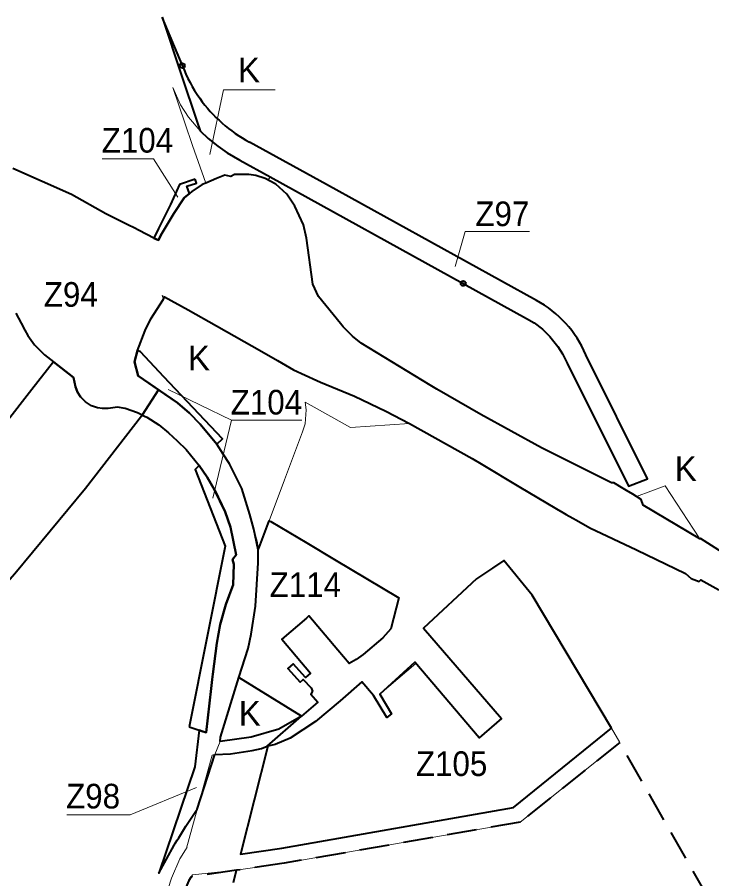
# Model space of a CAD drawing. Extents: x -650276 to -642489, y -1074311 to -1066658.
# Drawn here: x -646740 to -646064, y -1069193 to -1068354 of the extents above; entities that cross this region are included whole.
import ezdxf

# ---------------------------------------------------------------- set-up
doc = ezdxf.new("R2010")
doc.units = 0
doc.header["$LTSCALE"] = 9.6
doc.header["$PDMODE"] = 32
doc.header["$PDSIZE"] = 4.8
doc.linetypes.add('MEDIUM_DASHED', pattern=[4.5, 3, -1.5])
for name, color, linetype, lineweight in [('44', 7, 'Continuous', 40), ('45', 7, 'Continuous', 40), ('46', 7, 'Continuous', 13), ('47', 7, 'Continuous', 13), ('48', 7, 'Continuous', 13), ('61', 7, 'MEDIUM_DASHED', 40), ('63', 7, 'Continuous', 13)]:
    doc.layers.add(name, color=color, linetype=linetype, lineweight=lineweight)

msp = doc.modelspace()

# ---------------------------------------------------------------- linework, layer by layer
at = {"layer": '44'}
msp.add_line((-646578.881, -1068401.54), (-646598.635, -1068354.436), dxfattribs=at)
for points in [[(-646598.635, -1068354.436), (-646579.62, -1068411.29), (-646564.78, -1068455.41), (-646561.544, -1068464.842)], [(-646561.544, -1068464.842), (-646553.677, -1068472.283), (-646544.525, -1068479.79), (-646535.245, -1068486.342), (-646523.105, -1068493.54), (-646493.511, -1068509.855), (-646305.678, -1068613.404)], [(-646234.342, -1068629.893), (-646234.342, -1068629.892), (-646438.626, -1068517.274), (-646513.45, -1068476.025), (-646513.567, -1068475.963)], [(-646545.57, -1068511.42), (-646556.22, -1068515.84), (-646559.72, -1068517.29), (-646569.61, -1068524.1), (-646572.02, -1068526.07), (-646577.07, -1068530.2), (-646587.28, -1068545.28), (-646599.75, -1068566.49), (-646602.21, -1068571.5), (-646606.59, -1068569.33), (-646620.94, -1068561.96), (-646625.86, -1068559.47), (-646631.18, -1068556.77), (-646653.21, -1068545.58), (-646686.84, -1068526.89), (-646686.84, -1068526.89), (-646743.69, -1068501.76)], [(-646337.93, -1068712.4), (-646404.83, -1068671.52), (-646413.45, -1068664.71), (-646422.32, -1068655.58), (-646425.11, -1068652.37), (-646446.54, -1068626.14), (-646451.82, -1068614.31), (-646458.03, -1068569.26), (-646461.14, -1068556.34), (-646469.51, -1068538.15), (-646477.41, -1068526.45), (-646487.92, -1068516.87), (-646498.48, -1068511.26), (-646507.4, -1068508.45), (-646514.39, -1068507.56), (-646528.18, -1068507.58), (-646531.9, -1068509.25), (-646537.71, -1068508.16), (-646545.57, -1068511.42)], [(-646305.678, -1068613.404), (-646243.997, -1068647.407), (-646236.707, -1068651.891), (-646228.691, -1068658.051), (-646221.348, -1068665.144), (-646213.659, -1068674.696), (-646209.179, -1068681.795), (-646204.654, -1068690.937), (-646145.083, -1068810.83), (-646126.317, -1068803.654), (-646186.371, -1068682.825)], [(-646602.095, -1068716.98), (-646622.01, -1068703.3), (-646625.35, -1068689.7), (-646622.68, -1068678.75), (-646615.19, -1068659.11), (-646609.7, -1068647.84), (-646597.4, -1068628.74), (-646596.28, -1068626.52), (-646596.28, -1068626.52), (-646573.14, -1068638.98), (-646545.73, -1068654.81), (-646545.73, -1068654.81), (-646501.64, -1068679.81), (-646486.23, -1068688.54), (-646470.65, -1068697.38), (-646448.02, -1068707.99), (-646444.51, -1068709.64), (-646411.3, -1068723.11), (-646380.94, -1068737.81), (-646357.87, -1068749.64), (-646297.08, -1068783.8), (-646288.37, -1068789.04), (-646251.73, -1068811.04), (-646214.92, -1068832.85), (-646208.7, -1068836.39), (-646205.48, -1068838.23), (-646199.24, -1068841.79), (-646195.52, -1068843.92), (-646182.57, -1068851.3), (-646137.23, -1068872.6), (-646089.63, -1068895.5), (-646084.1, -1068900.51), (-646076.09, -1068903.48), (-646074.51, -1068901.9), (-646057.13, -1068911.62)], [(-646740.91, -1068642.34), (-646735.62, -1068652.21), (-646732.25, -1068659.06), (-646729.34, -1068663.94), (-646722.6, -1068673.11), (-646716.39, -1068679.8), (-646716.39, -1068679.8), (-646712.93, -1068683), (-646704.316, -1068689.698), (-646684.7, -1068704.95), (-646682.98, -1068714.07), (-646680.88, -1068719.28), (-646678.08, -1068723.7)], [(-646704.316, -1068689.698), (-646725.374, -1068716.786), (-646751.116, -1068749.975), (-646817.718, -1068830.545), (-646855.506, -1068872.883), (-646894.206, -1068911.595), (-646934.465, -1068940.759)], [(-646617.991, -1068741.504), (-646622.62, -1068739.32), (-646634.37, -1068735.27), (-646642.04, -1068733.74), (-646651.21, -1068734.99), (-646656.47, -1068735.13), (-646661.5, -1068734.35), (-646667.17, -1068732.38), (-646673.16, -1068728.69), (-646678.08, -1068723.7), (-646680.88, -1068719.28), (-646682.98, -1068714.07), (-646684.7, -1068704.95), (-646704.316, -1068689.698)], [(-646046.48, -1068879.92), (-646074.78, -1068861.51), (-646075.56, -1068861.95), (-646130.68, -1068829.21), (-646132.62, -1068823.54), (-646136.99, -1068820.88), (-646140.73, -1068818.61), (-646146.85, -1068814.88), (-646150.26, -1068812.81), (-646159.1, -1068807.43), (-646161.45, -1068807.54), (-646229.44, -1068773.53), (-646288.59, -1068740.88), (-646331.26, -1068716.25), (-646337.93, -1068712.4)], [(-646618.655, -1068742.359), (-646617.991, -1068741.504), (-646617.991, -1068741.503), (-646602.095, -1068716.98)], [(-646539.08, -1068779.481), (-646545.32, -1068769.89), (-646561.5, -1068750.22), (-646571.91, -1068739.54), (-646583.49, -1068729.76), (-646602.095, -1068716.98), (-646617.991, -1068741.503)], [(-647065.688, -1069087.73), (-646978.92, -1069073.93), (-646929.186, -1069052.925), (-646880.163, -1069024.903), (-646829.104, -1068987.917), (-646782.784, -1068941.581), (-646741.85, -1068895.719), (-646673.05, -1068812.491), (-646618.655, -1068742.359), (-646617.991, -1068741.504)], [(-646617.991, -1068741.503), (-646613.44, -1068743.65), (-646601.86, -1068751.01), (-646592.53, -1068758.66), (-646583.98, -1068766.42), (-646575.28, -1068775.04), (-646562.49, -1068790.69), (-646554.8, -1068801.98)], [(-646509.323, -1068852.529), (-646513.27, -1068838.37), (-646521.18, -1068812.95), (-646532.92, -1068788.95), (-646539.08, -1068779.481)], [(-646554.8, -1068801.98), (-646547.68, -1068814.22), (-646547.433, -1068814.73)], [(-646547.433, -1068814.73), (-646537.35, -1068835.56), (-646532.16, -1068850.47), (-646526.64, -1068877.47), (-646530.06, -1068882.16)], [(-646524, -1068997), (-646514.91, -1068968.48), (-646514.91, -1068968.48), (-646512.07, -1068954.68), (-646507.91, -1068927.47), (-646505.12, -1068885.31), (-646505.17, -1068872.78), (-646509.323, -1068852.529)], [(-646530.06, -1068882.16), (-646528.92, -1068886.55), (-646529.44, -1068906.81), (-646533.28, -1068917.17)], [(-646533.28, -1068917.17), (-646536.54, -1068925.95), (-646542.16, -1068945.12), (-646545.42, -1068963.3), (-646549.17, -1068993.71), (-646549.81, -1068998.88), (-646550.89, -1069007.7), (-646555.84, -1069050.22), (-646559.8, -1069048.98), (-646562.61, -1069048.08)], [(-646462.98, -1069034.61), (-646485, -1069047), (-646512, -1069055), (-646542, -1069059), (-646541.71, -1069054.76), (-646524, -1068997)], [(-646547.412, -1069071.71), (-646532, -1069071), (-646511, -1069068), (-646502, -1069066), (-646496.317, -1069063.61), (-646462.98, -1069034.61)], [(-646562.61, -1069048.08), (-646566.82, -1069083.62), (-646601.82, -1069187.25), (-646586.97, -1069160.06), (-646585.42, -1069157.56), (-646583.89, -1069155.1), (-646582.46, -1069152.81), (-646582.46, -1069152.81), (-646575.4, -1069141.46), (-646564.54, -1069125.08), (-646547.412, -1069071.71)]]:
    msp.add_lwpolyline(points, dxfattribs=at)
at = {"layer": '44', "lineweight": 13}
for points in [[(-646241.379, -1068562.947), (-646303.746, -1068562.947), (-646313.477, -1068597.03)], [(-646241.379, -1068562.947), (-646303.746, -1068562.947), (-646313.477, -1068597.03)], [(-646691.216, -1069130.395), (-646629.734, -1069130.395), (-646565.156, -1069103.837)], [(-646691.216, -1069130.395), (-646629.734, -1069130.395), (-646565.156, -1069103.837)]]:
    msp.add_lwpolyline(points, dxfattribs=at)
at = {"layer": '44'}
for centre, radius, start, end in [((-646447.332, -1068351.964), 140.58, 200.6496, 215.36619), ((-646447.332, -1068351.964), 140.58, 215.36631, 241.891), ((-646287.447, -1068726.224), 110, 23.23727, 61.13296)]:
    msp.add_arc(centre, radius, start, end, dxfattribs=at)
for p in [(-646578.881, -1068401.54), (-646305.678, -1068613.404)]:
    msp.add_point(p, dxfattribs=at)
at = {"layer": '45'}
msp.add_line((-646583.49, -1068729.76), (-646571.91, -1068739.54), dxfattribs=at)
msp.add_line((-646583.49, -1068729.76), (-646571.91, -1068739.54), dxfattribs=at)
for points in [[(-646566.33, -1068512.04), (-646581.64, -1068517.24), (-646590.31, -1068536.69), (-646602.01, -1068560.15), (-646606.59, -1068569.33)], [(-646566.33, -1068512.04), (-646581.64, -1068517.24), (-646590.31, -1068536.69), (-646602.01, -1068560.15), (-646606.59, -1068569.33)], [(-646587.28, -1068545.28), (-646577.07, -1068530.2), (-646572.02, -1068526.07), (-646574.48, -1068518.75), (-646565.04, -1068515.86), (-646566.33, -1068512.04)], [(-646587.28, -1068545.28), (-646577.07, -1068530.2), (-646572.02, -1068526.07), (-646574.48, -1068518.75), (-646565.04, -1068515.86), (-646566.33, -1068512.04)], [(-646599.75, -1068566.49), (-646587.28, -1068545.28), (-646587.28, -1068545.28)], [(-646599.75, -1068566.49), (-646587.28, -1068545.28), (-646587.28, -1068545.28)], [(-646606.59, -1068569.33), (-646602.21, -1068571.5), (-646599.75, -1068566.49)], [(-646606.59, -1068569.33), (-646602.21, -1068571.5), (-646599.75, -1068566.49)], [(-646571.91, -1068739.54), (-646561.5, -1068750.22), (-646545.32, -1068769.89), (-646539.78, -1068764.65), (-646596.93, -1068704.15), (-646619.74, -1068680.15), (-646622.68, -1068678.75), (-646625.35, -1068689.7)], [(-646571.91, -1068739.54), (-646561.5, -1068750.22), (-646545.32, -1068769.89), (-646539.78, -1068764.65), (-646596.93, -1068704.15), (-646619.74, -1068680.15), (-646622.68, -1068678.75), (-646625.35, -1068689.7)], [(-646625.35, -1068689.7), (-646622.01, -1068703.3), (-646583.49, -1068729.76)], [(-646625.35, -1068689.7), (-646622.01, -1068703.3), (-646583.49, -1068729.76)], [(-646562.49, -1068790.69), (-646566.34, -1068794.32), (-646537.3, -1068868.95), (-646572.42, -1069044.94)], [(-646562.49, -1068790.69), (-646566.34, -1068794.32), (-646537.3, -1068868.95), (-646572.42, -1069044.94)], [(-646526.64, -1068877.47), (-646532.16, -1068850.47), (-646537.35, -1068835.56), (-646547.68, -1068814.22), (-646554.8, -1068801.98), (-646562.49, -1068790.69)], [(-646526.64, -1068877.47), (-646532.16, -1068850.47), (-646537.35, -1068835.56), (-646547.68, -1068814.22), (-646554.8, -1068801.98), (-646562.49, -1068790.69)], [(-646529.44, -1068906.81), (-646528.92, -1068886.55), (-646530.06, -1068882.16), (-646526.64, -1068877.47)], [(-646529.44, -1068906.81), (-646528.92, -1068886.55), (-646530.06, -1068882.16), (-646526.64, -1068877.47)], [(-646555.84, -1069050.22), (-646550.89, -1069007.7), (-646549.81, -1068998.88), (-646549.17, -1068993.71), (-646545.42, -1068963.3), (-646542.16, -1068945.12), (-646536.54, -1068925.95), (-646533.28, -1068917.17), (-646529.44, -1068906.81)], [(-646555.84, -1069050.22), (-646550.89, -1069007.7), (-646549.81, -1068998.88), (-646549.17, -1068993.71), (-646545.42, -1068963.3), (-646542.16, -1068945.12), (-646536.54, -1068925.95), (-646533.28, -1068917.17), (-646529.44, -1068906.81)], [(-646572.42, -1069044.94), (-646562.61, -1069048.08), (-646559.8, -1069048.98), (-646555.84, -1069050.22)], [(-646572.42, -1069044.94), (-646562.61, -1069048.08), (-646559.8, -1069048.98), (-646555.84, -1069050.22)]]:
    msp.add_lwpolyline(points, dxfattribs=at)
for points in [[(-646512.07, -1068954.68), (-646507.91, -1068927.47), (-646505.12, -1068885.31), (-646505.17, -1068872.78), (-646503.24, -1068867.61), (-646494.52, -1068844.29), (-646492.73, -1068845.01), (-646457.86, -1068865.8), (-646430.86, -1068881.89), (-646368.3, -1068919.19), (-646376.02, -1068949.34), (-646383.86, -1068958.24), (-646403.13, -1068974.41), (-646409.67, -1068979.3), (-646416.71, -1068983.21), (-646427.77, -1068970.39), (-646455.78, -1068936.87), (-646458.21, -1068938.99), (-646482.2, -1068959.52), (-646454.21, -1068992.73), (-646459.25, -1068996.98), (-646471.24, -1068983.41), (-646476.35, -1068987.98), (-646464.24, -1069001.49), (-646461.29, -1068998.81), (-646453.48, -1069006.75), (-646452.37, -1069010.01), (-646453.88, -1069013.1), (-646447.2, -1069020.9), (-646462.98, -1069034.61), (-646524, -1068997), (-646514.91, -1068968.48), (-646514.91, -1068968.48)], [(-646512.07, -1068954.68), (-646507.91, -1068927.47), (-646505.12, -1068885.31), (-646505.17, -1068872.78), (-646503.24, -1068867.61), (-646494.52, -1068844.29), (-646492.73, -1068845.01), (-646457.86, -1068865.8), (-646430.86, -1068881.89), (-646368.3, -1068919.19), (-646376.02, -1068949.34), (-646383.86, -1068958.24), (-646403.13, -1068974.41), (-646409.67, -1068979.3), (-646416.71, -1068983.21), (-646427.77, -1068970.39), (-646455.78, -1068936.87), (-646458.21, -1068938.99), (-646482.2, -1068959.52), (-646454.21, -1068992.73), (-646459.25, -1068996.98), (-646471.24, -1068983.41), (-646476.35, -1068987.98), (-646464.24, -1069001.49), (-646461.29, -1068998.81), (-646453.48, -1069006.75), (-646452.37, -1069010.01), (-646453.88, -1069013.1), (-646447.2, -1069020.9), (-646462.98, -1069034.61), (-646524, -1068997), (-646514.91, -1068968.48), (-646514.91, -1068968.48)], [(-646161.484, -1069046.228), (-646238.632, -1068916.799), (-646266.118, -1068883.048), (-646277.268, -1068890.446), (-646292.75, -1068900.72), (-646344.49, -1068948.736), (-646268.528, -1069036.82), (-646290.099, -1069055.423), (-646352.71, -1068981.82), (-646386.936, -1069012.936), (-646375.346, -1069032.07), (-646379.973, -1069035.889), (-646393.09, -1069014.234), (-646404.269, -1069001.033), (-646425.52, -1069019.41), (-646449.418, -1069039.804), (-646474.13, -1069055.83), (-646488.537, -1069062.169), (-646495.89, -1069063.531), (-646522.35, -1069168.648), (-646482.211, -1069162.813), (-646256.824, -1069123.414)], [(-646161.484, -1069046.228), (-646238.632, -1068916.799), (-646266.118, -1068883.048), (-646277.268, -1068890.446), (-646292.75, -1068900.72), (-646344.49, -1068948.736), (-646268.528, -1069036.82), (-646290.099, -1069055.423), (-646352.71, -1068981.82), (-646386.936, -1069012.936), (-646375.346, -1069032.07), (-646379.973, -1069035.889), (-646393.09, -1069014.234), (-646404.269, -1069001.033), (-646425.52, -1069019.41), (-646449.418, -1069039.804), (-646474.13, -1069055.83), (-646488.537, -1069062.169), (-646495.89, -1069063.531), (-646522.35, -1069168.648), (-646482.211, -1069162.813), (-646256.824, -1069123.414)]]:
    msp.add_lwpolyline(points, close=True, dxfattribs=at)
at = {"layer": '46'}
for points in [[(-646656.853, -1068492.089), (-646606.877, -1068492.089), (-646583.419, -1068529.344)], [(-646656.853, -1068492.089), (-646606.877, -1068492.089), (-646583.419, -1068529.344)], [(-646462.83, -1068746.366), (-646531.233, -1068746.366), (-646549.233, -1068822.328), (-646531.233, -1068746.366), (-646592.58, -1068716.54)], [(-646462.83, -1068746.366), (-646531.233, -1068746.366), (-646549.233, -1068822.328), (-646531.233, -1068746.366), (-646592.58, -1068716.54)]]:
    msp.add_lwpolyline(points, dxfattribs=at)
at = {"layer": '47'}
msp.add_line((-646462.98, -1069034.61), (-646524, -1068997), dxfattribs=at)
for points in [[(-646561.544, -1068464.842), (-646572.984, -1068451.81), (-646580.625, -1068439.803), (-646588.07, -1068422.96), (-646576.4, -1068457.27), (-646568.87, -1068479.14), (-646556.22, -1068515.84), (-646545.57, -1068511.42), (-646537.71, -1068508.16)], [(-646523.105, -1068493.54), (-646535.245, -1068486.342), (-646544.525, -1068479.79), (-646553.677, -1068472.283), (-646561.544, -1068464.842)], [(-646537.71, -1068508.16), (-646531.9, -1068509.25), (-646528.18, -1068507.58), (-646514.39, -1068507.56), (-646507.4, -1068508.45), (-646498.48, -1068511.26), (-646495.416, -1068512.888), (-646493.511, -1068509.855), (-646523.105, -1068493.54)], [(-646075.56, -1068861.95), (-646130.68, -1068829.21), (-646132.62, -1068823.54), (-646136.99, -1068820.88), (-646109.35, -1068810.23)], [(-646109.35, -1068810.23), (-646081.72, -1068852.51), (-646075.56, -1068861.95)], [(-646524, -1068997), (-646541.71, -1069054.76), (-646542, -1069059), (-646547.412, -1069071.71)], [(-646495.89, -1069063.531), (-646496.317, -1069063.61), (-646496.317, -1069063.61), (-646462.98, -1069034.61)], [(-646593.793, -1069255.911), (-646577.878, -1069206.485), (-646572.586, -1069194.485), (-646569.114, -1069188.86), (-646526.31, -1069184.381), (-646479.84, -1069177.626), (-646250.409, -1069137.52), (-646153.307, -1069059.947), (-646161.484, -1069046.228), (-646256.824, -1069123.414)], [(-646256.824, -1069123.414), (-646482.211, -1069162.813), (-646522.35, -1069168.648), (-646495.89, -1069063.531)], [(-646547.412, -1069071.71), (-646549.91, -1069072.542), (-646564.54, -1069125.08), (-646564.605, -1069125.271), (-646574.978, -1069163.017), (-646574.978, -1069163.017), (-646574.33, -1069162.04), (-646575.87, -1069164.54), (-646581.29, -1069173.32), (-646589.56, -1069192.07), (-646601.41, -1069229.34)]]:
    msp.add_lwpolyline(points, dxfattribs=at)
msp.add_lwpolyline([(-646513.27, -1068838.37), (-646505.69, -1068865.56), (-646505.17, -1068872.78), (-646503.24, -1068867.61), (-646494.52, -1068844.29), (-646479.45, -1068804.37), (-646461.92, -1068757.93), (-646459.59, -1068750.19), (-646458.57, -1068736.31), (-646459.54, -1068728.94), (-646453.51, -1068732.3), (-646415.3, -1068753.62), (-646357.87, -1068749.64), (-646411.3, -1068723.11), (-646448.02, -1068707.99), (-646470.65, -1068697.38), (-646486.23, -1068688.54), (-646501.64, -1068679.81), (-646545.73, -1068654.81), (-646573.14, -1068638.98), (-646598.59, -1068625.34), (-646597.4, -1068628.74), (-646609.7, -1068647.84), (-646615.19, -1068659.11), (-646622.68, -1068678.75), (-646619.74, -1068680.15), (-646596.93, -1068704.15), (-646539.78, -1068764.65), (-646545.32, -1068769.89), (-646532.92, -1068788.95), (-646521.18, -1068812.95)], close=True, dxfattribs=at)
at = {"layer": '48'}
msp.add_lwpolyline([(-646488.64, -1068425), (-646538.869, -1068425), (-646552.014, -1068487.951)], dxfattribs=at)
msp.add_lwpolyline([(-646488.64, -1068425), (-646538.869, -1068425), (-646552.014, -1068487.951)], dxfattribs=at)
at = {"layer": '61'}
for points in [[(-646583.457, -1069759.191), (-646554.262, -1069762.602), (-646321.973, -1069686.855), (-646209.9, -1069538.5), (-646146.8, -1069506.6), (-646148.5, -1069503), (-646028.16, -1069441.58), (-646023.96, -1069440.34), (-646075.49, -1069318.19), (-646025.14, -1069285.394), (-646153.307, -1069059.947)], [(-646153.307, -1069059.947), (-646250.409, -1069137.52), (-646479.84, -1069177.626), (-646526.31, -1069184.381)]]:
    msp.add_lwpolyline(points, dxfattribs=at)
msp.add_lwpolyline([(-646572.586, -1069194.485), (-646577.878, -1069206.485), (-646611.107, -1069309.68), (-646626.774, -1069359.349), (-646580.797, -1069364.111), (-646571.479, -1069363.822), (-646526.31, -1069184.381), (-646570.296, -1069190.776)], close=True, dxfattribs=at)
at = {"layer": '63'}
for points in [[(-646494.52, -1068844.29), (-646505.17, -1068872.78), (-646505.12, -1068885.31), (-646507.91, -1068927.47)], [(-646447.2, -1069020.9), (-646449.47, -1069018.25), (-646453.88, -1069013.1), (-646452.37, -1069010.01), (-646453.48, -1069006.75), (-646461.29, -1068998.81), (-646464.24, -1069001.49), (-646476.35, -1068987.98), (-646471.24, -1068983.41), (-646459.25, -1068996.98), (-646454.21, -1068992.73), (-646482.2, -1068959.52), (-646468.83, -1068948.26), (-646455.78, -1068936.87), (-646427.77, -1068970.39), (-646416.71, -1068983.21), (-646409.67, -1068979.3), (-646403.13, -1068974.41), (-646383.86, -1068958.24), (-646376.02, -1068949.34), (-646368.3, -1068919.19), (-646430.86, -1068881.89), (-646457.86, -1068865.8), (-646492.73, -1068845.01), (-646494.52, -1068844.29)], [(-646256.824, -1069123.414), (-646161.484, -1069046.228), (-646238.632, -1068916.799), (-646266.118, -1068883.048), (-646292.75, -1068900.72), (-646344.49, -1068948.736)], [(-646507.91, -1068927.47), (-646512.07, -1068954.68), (-646514.91, -1068968.48), (-646516.039, -1068972.022), (-646524, -1068997), (-646462.98, -1069034.61), (-646447.2, -1069020.9)], [(-646344.49, -1068948.736), (-646268.528, -1069036.82), (-646290.099, -1069055.423), (-646305.65, -1069037.39), (-646351.641, -1068983.083), (-646386.936, -1069012.936), (-646375.346, -1069032.07), (-646379.973, -1069035.889), (-646393.09, -1069014.234), (-646404.269, -1069001.033), (-646410.96, -1069006.99), (-646425.52, -1069019.41)], [(-646425.52, -1069019.41), (-646449.418, -1069039.804), (-646474.13, -1069055.83), (-646488.537, -1069062.169), (-646495.89, -1069063.531), (-646522.35, -1069168.648), (-646482.211, -1069162.813), (-646256.824, -1069123.414), (-646256.824, -1069123.414)]]:
    msp.add_lwpolyline(points, dxfattribs=at)

# ---------------------------------------------------------------- texts
at = {"layer": '44', "width": 0.95}
for s, p in [('Z97', (-646293.907, -1068557.715)), ('Z97', (-646293.907, -1068557.715)), ('Z94', (-646713.687, -1068636.144)), ('Z94', (-646713.687, -1068636.144)), ('Z98', (-646691.993, -1069124.279)), ('Z98', (-646691.993, -1069124.279))]:
    msp.add_text(s, height=24, dxfattribs=at).set_placement(p)
at = {"layer": '46', "width": 0.95}
for s, p in [('Z104', (-646657.338, -1068486.184)), ('Z104', (-646657.338, -1068486.184)), ('Z104', (-646531.893, -1068740.983)), ('Z104', (-646531.893, -1068740.983)), ('Z114', (-646493.997, -1068918.587)), ('Z114', (-646493.997, -1068918.587)), ('Z105', (-646351.762, -1069092.692)), ('Z105', (-646351.762, -1069092.692))]:
    msp.add_text(s, height=24, dxfattribs=at).set_placement(p)
at = {"layer": '48'}
for p in [(-646524.8, -1068417.662), (-646524.8, -1068417.662), (-646573.463, -1068697.908), (-646573.463, -1068697.908), (-646099.972, -1068805.526), (-646524.065, -1069043.743), (-646524.065, -1069043.743)]:
    msp.add_text('K', height=24, dxfattribs=at).set_placement(p)

doc.saveas('drawing.dxf')
